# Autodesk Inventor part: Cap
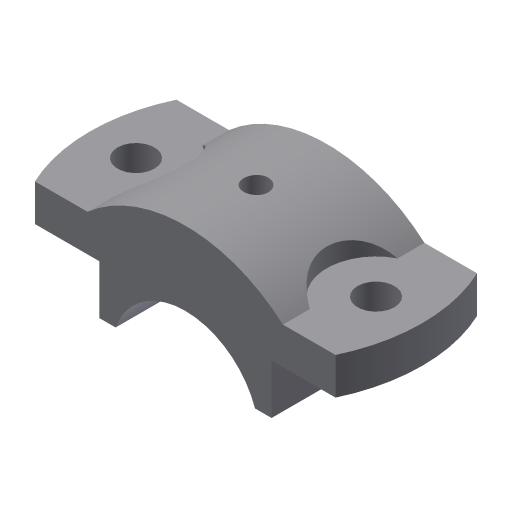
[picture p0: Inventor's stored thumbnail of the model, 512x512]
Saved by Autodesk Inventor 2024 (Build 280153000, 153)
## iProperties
Created: 2009-04
Part Number: Cap
Document SubType Name: Modeling
Designer: Sham
Density: 1 g/cm^3
Material: Generic
Appearance: Default
Author: Sham
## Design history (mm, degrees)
sketch "Sketch1"
  geometry: L1 (-48.857, 23)-(48.857, 23); L2 (48.857, -23)-(-48.857, -23); A1 r 54 centre (0, 0) between (-48.857, 23) and (-48.857, -23); A2 r 54 centre (0, 0) between (48.857, -23) and (48.857, 23); 1 further point
  constraints: 4 end point, 4 point on circle, 2 centre point, 2 coincident, 1 horizontal, 1 parallel, 1 other
  dimensions: "d3" = 54 radius of A1; "d4" = 54 radius of A2; "d5" = 46 distance between parallel lines of L2 L1; "d6" = 23 distance from line of point (0, 0) L1
extrude "Extrusion1" new body sketch "Sketch1" distance "d7" = 12; taper "d8" = 0 deg
sketch "Sketch3"
  geometry: L1 (20.906, 0)-(20.906, -16); L2 (76.906, -0.137)-(76.906, -16.137); L3 (20.906, -16)-(26.23, -16); L4 (71.532, -16.137)-(76.906, -16.137); L5 (76.906, -0.137)-(76.857, 12); L6 (97.714, 0)-(0, 0) reference; L7 (76.857, 12)-(80.606, 12); L8 (17.108, 12)-(20.906, 12); L9 (20.906, 12)-(20.906, 0); L10 (0, 12)-(97.714, 12) reference; A1 r 24 centre (48.857, -24) between (71.532, -16.137) and (26.23, -16); A2 r 48 centre (48.857, -24) between (80.606, 12) and (17.108, 12); 3 further points
  constraints: 16 end point, 4 point on circle, 3 parallel, 3 perpendicular, 2 centre point, 2 coincident, 2 vertical alignment, 1 collinear, 1 midpoint, 1 vertical, 2 other
  dimensions: "d17" = 48 diameter of A1; "d18" = 16 distance of L1.start L1.end; "d19" = 56 distance between parallel lines of L2 L1; "d21" = 8 vertical distance of A1.centre L1.end; "d22" = 48 radius of A2; "d23" = 0 distance from line of L6 L1.start; "d38" = 31.74902 distance of L7.end point (48.857, 12); "d39" = 28 distance from line of point (48.857, 12) L5
extrude "Extrusion2" join sketch "Sketch3" stored distance "d24" = 12; taper "d25" = 0 deg
sketch "Sketch4"
  geometry: 2 further points
  dimensions: "d26" = 78 distance of point (39, 0) point (-39, 0)
hole "Hole1" sketch "Sketch4" at (-39, 0), (39, 0) diameter "d28" = 12; stored, may be unused: countersink angle "d32" = 90 deg, drill point angle "d34" = 118 deg; dims "d29" = 6, "d30" = 4, "d31" = 2, "d33" = 8
sketch "Sketch5"
  geometry: L1 (-31.749, -23)-(-31.749, 23) reference; L2 (-31.749, 14.263)-(-31.749, -14.263); C1 r 6 at (-39, 0) reference; A1 r 16 centre (-39, 0) between (-31.749, -14.263) and (-31.749, 14.263)
  constraints: 2 end point, 2 point on circle, 1 centre point, 1 coincident, 1 collinear, 1 point on line
  dimensions: "d35" = 16 radius of A1
extrude "Extrusion3" cut sketch "Sketch5" distance "d36" = 12; taper "d37" = 0 deg
mirror "Mirror2"
workplane "Work Plane4"
sketch "Sketch6"
  geometry: L1 (-31.749, 0)-(31.749, 0) reference; 1 further point
  dimensions: "d40" = 23 distance from line of L1 point (0, 23)
hole "Hole2" sketch "Sketch6" at (0, 23) diameter "d41" = 6; stored, may be unused: countersink angle "d45" = 90 deg, drill point angle "d47" = 118 deg; dims "d42" = 6, "d43" = 8, "d44" = 16, "d46" = 8
body "Solid1"
